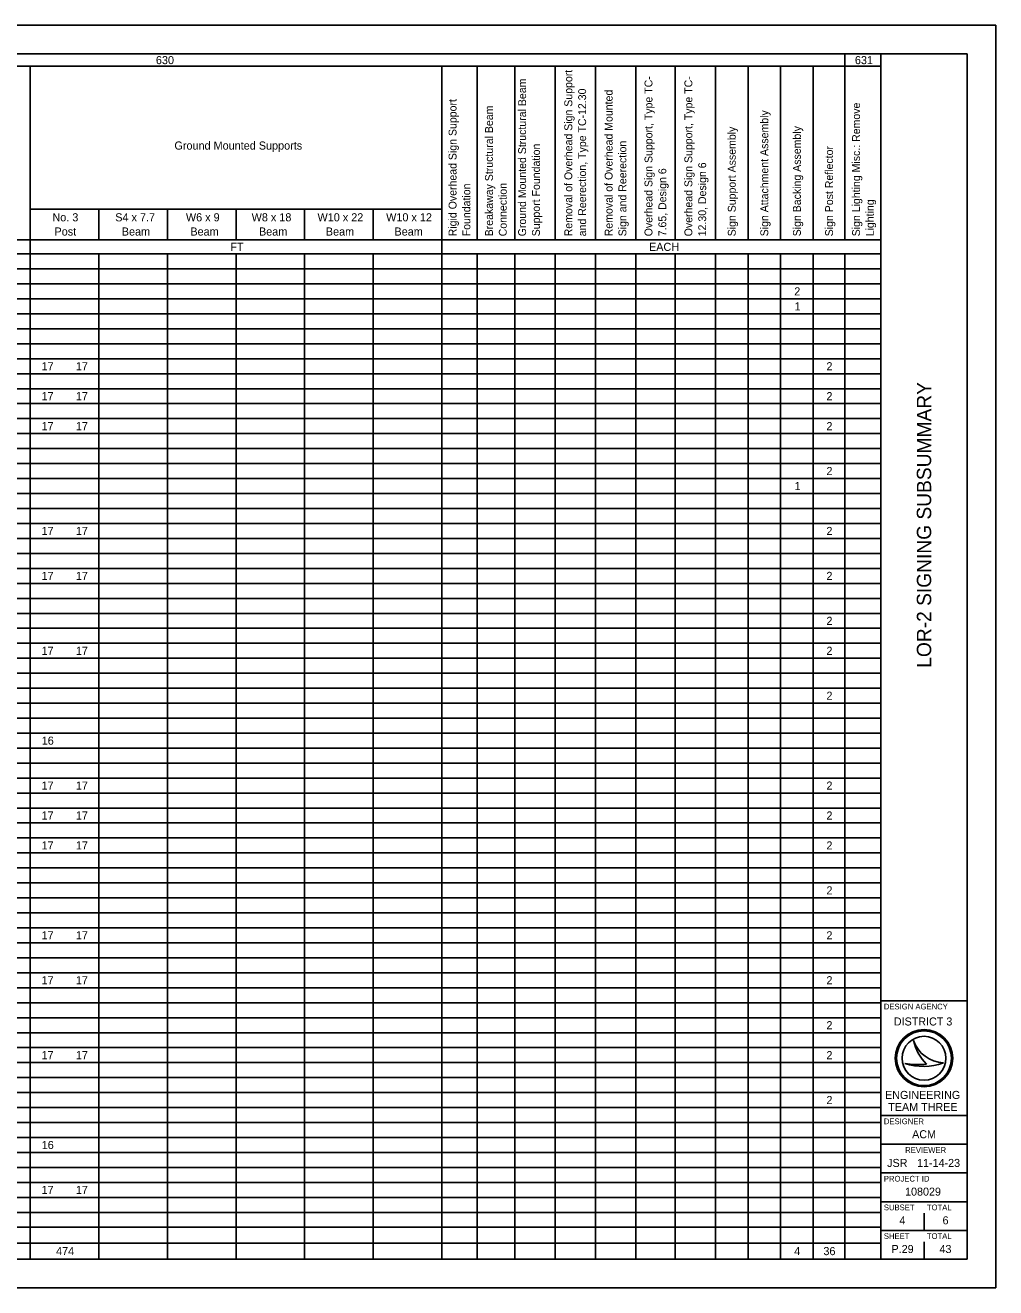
# Model space of a CAD drawing. Extents: x 0 to 34, y 0 to 22.
# Drawn here: x 17.09 to 34, y 0 to 22 of the extents above; entities that cross this region are included whole.
import ezdxf

# ---------------------------------------------------------------- set-up
doc = ezdxf.new("R2010")
doc.units = 0
for name, color, linetype in [('SH_Border', 7, 'Continuous'), ('SH_Cut_Line', 7, 'Continuous'), ('SH_Data', 7, 'Continuous'), ('SH_Text', 7, 'Continuous')]:
    doc.layers.add(name, color=color, linetype=linetype)

msp = doc.modelspace()

# ---------------------------------------------------------------- linework, layer by layer
at = {"layer": 'SH_Border'}
for p, q in [((32, 0.5), (32, 21.5)), ((32, 5), (33.5, 5)), ((32, 3), (33.5, 3)), ((32, 2.5), (33.5, 2.5)), ((32, 2), (33.5, 2)), ((32, 1.5), (33.5, 1.5)), ((32, 1), (33.5, 1))]:
    msp.add_line(p, q, dxfattribs=at)
msp.add_lwpolyline([(1.5, 21.5), (33.5, 21.5), (33.5, 0.5), (1.5, 0.5)], close=True, dxfattribs=at)
at = {"layer": 'SH_Cut_Line'}
msp.add_lwpolyline([(0, 0), (34, 0), (34, 22), (0, 22)], close=True, dxfattribs=at)
at = {"layer": 'SH_Data'}
for p, q in [((32.567, 4.31), (32.567, 4.31)), ((32.75, 4), (32.75, 4)), ((32.417, 3.91), (32.417, 3.91)), ((33.087, 3.919), (33.087, 3.919)), ((32.75, 1), (32.75, 1.3)), ((32.375, 0.675), (32.375, 0.675)), ((32.75, 0.5), (32.75, 0.8))]:
    msp.add_line(p, q, dxfattribs=at)
for radius in [0.5, 0.477, 0.477, 0.382]:
    msp.add_circle((32.75, 4), radius, dxfattribs=at)
for centre, radius, start, end in [((33.116, 4.498), 0.58, 198.9257, 198.9319), ((33.347, 4.47), 0.796, 191.6379, 191.6421), ((33.116, 4.498), 0.58, 198.9319, 267.1657), ((33.347, 4.47), 0.796, 191.6421, 226.0947), ((32.739, 4.87), 1.013, 251.4576, 290.0832), ((32.648, 5.154), 1.266, 259.4964, 259.4995), ((32.739, 4.87), 1.013, 251.4527, 251.4576), ((32.648, 5.154), 1.266, 259.4995, 276.6672)]:
    msp.add_arc(centre, radius, start, end, dxfattribs=at)
at = {"layer": 'SH_Text'}
for p, q in [((1.5, 21.5), (32, 21.5)), ((31.372, 21.5), (31.372, 18.261)), ((32, 21.5), (32, 18.015)), ((7.657, 21.285), (32, 21.285)), ((17.176, 21.285), (17.176, 18.015)), ((24.349, 21.285), (24.349, 18.015)), ((24.962, 21.285), (24.962, 18.261)), ((25.619, 21.285), (25.619, 18.261)), ((26.321, 21.285), (26.321, 18.261)), ((27.024, 21.285), (27.024, 18.261)), ((27.726, 21.285), (27.726, 18.261)), ((28.414, 21.285), (28.414, 18.261)), ((29.116, 21.285), (29.116, 18.261)), ((29.684, 21.285), (29.684, 18.261)), ((30.252, 21.285), (30.252, 18.261)), ((30.819, 21.285), (30.819, 18.261)), ((17.176, 18.798), (24.349, 18.798)), ((18.371, 18.798), (18.371, 18.261)), ((19.567, 18.798), (19.567, 18.261)), ((20.762, 18.798), (20.762, 18.261)), ((21.958, 18.798), (21.958, 18.261)), ((23.153, 18.798), (23.153, 18.261)), ((6.521, 18.261), (32, 18.261)), ((1.5, 18.015), (32, 18.015)), ((17.176, 18.015), (17.176, 0.5)), ((18.371, 18.015), (18.371, 0.5)), ((19.567, 18.015), (19.567, 0.5)), ((20.762, 18.015), (20.762, 0.5)), ((21.958, 18.015), (21.958, 0.5)), ((23.153, 18.015), (23.153, 0.5)), ((24.349, 18.015), (24.349, 0.5)), ((24.962, 18.015), (24.962, 0.5)), ((25.619, 18.015), (25.619, 0.5)), ((26.321, 18.015), (26.321, 0.5)), ((27.024, 18.015), (27.024, 0.5)), ((27.726, 18.015), (27.726, 0.5)), ((28.414, 18.015), (28.414, 0.5)), ((29.116, 18.015), (29.116, 0.5)), ((29.684, 18.015), (29.684, 0.5)), ((30.252, 18.015), (30.252, 0.5)), ((30.819, 18.015), (30.819, 0.5)), ((31.372, 18.015), (31.372, 0.5)), ((32, 18.015), (32, 0.5)), ((1.5, 17.754), (32, 17.754)), ((1.5, 17.493), (32, 17.493)), ((1.5, 17.232), (32, 17.232)), ((1.5, 16.971), (32, 16.971)), ((1.5, 16.711), (32, 16.711)), ((1.5, 16.45), (32, 16.45)), ((1.5, 16.189), (32, 16.189)), ((1.5, 15.928), (32, 15.928)), ((1.5, 15.667), (32, 15.667)), ((1.5, 15.406), (32, 15.406)), ((1.5, 15.145), (32, 15.145)), ((1.5, 14.884), (32, 14.884)), ((1.5, 14.623), (32, 14.623)), ((1.5, 14.362), (32, 14.362)), ((1.5, 14.101), (32, 14.101)), ((1.5, 13.84), (32, 13.84)), ((1.5, 13.579), (32, 13.579)), ((1.5, 13.318), (32, 13.318)), ((1.5, 13.057), (32, 13.057)), ((1.5, 12.796), (32, 12.796)), ((1.5, 12.535), (32, 12.535)), ((1.5, 12.274), (32, 12.274)), ((1.5, 12.013), (32, 12.013)), ((1.5, 11.752), (32, 11.752)), ((1.5, 11.491), (32, 11.491)), ((1.5, 11.23), (32, 11.23)), ((1.5, 10.969), (32, 10.969)), ((1.5, 10.708), (32, 10.708)), ((1.5, 10.447), (32, 10.447)), ((1.5, 10.186), (32, 10.186)), ((1.5, 9.925), (32, 9.925)), ((1.5, 9.664), (32, 9.664)), ((1.5, 9.404), (32, 9.404)), ((1.5, 9.143), (32, 9.143)), ((1.5, 8.882), (32, 8.882)), ((1.5, 8.621), (32, 8.621)), ((1.5, 8.36), (32, 8.36)), ((1.5, 8.099), (32, 8.099)), ((1.5, 7.838), (32, 7.838)), ((1.5, 7.577), (32, 7.577)), ((1.5, 7.316), (32, 7.316)), ((1.5, 7.055), (32, 7.055)), ((1.5, 6.794), (32, 6.794)), ((1.5, 6.533), (32, 6.533)), ((1.5, 6.272), (32, 6.272)), ((1.5, 6.011), (32, 6.011)), ((1.5, 5.75), (32, 5.75)), ((1.5, 5.489), (32, 5.489)), ((1.5, 5.228), (32, 5.228)), ((1.5, 4.967), (32, 4.967)), ((1.5, 4.706), (32, 4.706)), ((1.5, 4.445), (32, 4.445)), ((1.5, 4.184), (32, 4.184)), ((1.5, 3.923), (32, 3.923)), ((1.5, 3.662), (32, 3.662)), ((1.5, 3.401), (32, 3.401)), ((1.5, 3.14), (32, 3.14)), ((1.5, 2.879), (32, 2.879)), ((1.5, 2.618), (32, 2.618)), ((1.5, 2.357), (32, 2.357)), ((1.5, 2.096), (32, 2.096)), ((1.5, 1.836), (32, 1.836)), ((1.5, 1.575), (32, 1.575)), ((1.5, 1.314), (32, 1.314)), ((1.5, 1.053), (32, 1.053)), ((1.5, 0.776), (32, 0.776)), ((1.5, 0.5), (32, 0.5))]:
    msp.add_line(p, q, dxfattribs=at)

# ---------------------------------------------------------------- texts
at = {"layer": 'SH_Data'}
msp.add_text('LOR-2 SIGNING SUBSUMMARY', height=0.25, rotation=90, dxfattribs=at).set_placement((32.875, 10.804))
for s, height, p in [('DESIGN AGENCY', 0.1, (32.05, 4.85)), ('DISTRICT 3', 0.14, (32.224, 4.57)), ('ENGINEERING', 0.14, (32.071, 3.29)), ('TEAM THREE', 0.14, (32.127, 3.08)), ('DESIGNER', 0.1, (32.05, 2.85)), ('ACM', 0.14, (32.543, 2.605)), ('REVIEWER', 0.1, (32.422, 2.35)), ('JSR', 0.14, (32.108, 2.105)), ('11-14-23', 0.14, (32.629, 2.105)), ('PROJECT ID', 0.1, (32.05, 1.85)), ('SUBSET', 0.1, (32.05, 1.35)), ('TOTAL', 0.1, (32.8, 1.35)), ('4', 0.14, (32.322, 1.105)), ('6', 0.14, (33.073, 1.105)), ('SHEET', 0.1, (32.05, 0.85)), ('TOTAL', 0.1, (32.8, 0.85)), ('P.29', 0.14, (32.184, 0.605)), ('43', 0.14, (33.02, 0.605))]:
    msp.add_text(s, height=height, dxfattribs=at).set_placement(p)
at = {"layer": 'SH_Text'}
for s, height, p in [('630', 0.1412, (19.366, 21.322)), ('631', 0.1412, (31.546, 21.322)), ('Ground Mounted Supports', 0.14123, (19.689, 19.833)), ('No. 3', 0.1412, (17.563, 18.583)), ('S4 x 7.7', 0.1412, (18.658, 18.583)), ('W6 x 9', 0.1412, (19.889, 18.583)), ('W8 x 18', 0.1412, (21.034, 18.583)), ('W10 x 22 ', 0.1412, (22.182, 18.583)), ('W10 x 12 ', 0.1412, (23.378, 18.583)), ('Post', 0.1412, (17.599, 18.335)), (' Beam', 0.1412, (18.719, 18.335)), (' Beam', 0.1412, (19.914, 18.335)), (' Beam', 0.1412, (21.11, 18.335)), ('Beam', 0.1412, (22.327, 18.335)), ('Beam', 0.1412, (23.523, 18.335)), ('FT', 0.1412, (20.663, 18.068)), ('EACH', 0.1412, (27.958, 18.068)), ('2', 0.141, (30.489, 17.292)), ('1', 0.141, (30.495, 17.031)), ('17', 0.1412, (17.373, 15.987)), ('17', 0.1412, (17.971, 15.987)), ('2', 0.141, (31.05, 15.987)), ('17', 0.1412, (17.373, 15.466)), ('17', 0.1412, (17.971, 15.466)), ('2', 0.141, (31.05, 15.466)), ('17', 0.1412, (17.373, 14.944)), ('17', 0.1412, (17.971, 14.944)), ('2', 0.141, (31.05, 14.944)), ('2', 0.141, (31.05, 14.161)), ('1', 0.141, (30.495, 13.9)), ('17', 0.1412, (17.373, 13.117)), ('17', 0.1412, (17.971, 13.117)), ('2', 0.141, (31.05, 13.117)), ('17', 0.1412, (17.373, 12.334)), ('17', 0.1412, (17.971, 12.334)), ('2', 0.141, (31.05, 12.334)), ('2', 0.141, (31.05, 11.551)), ('17', 0.1412, (17.373, 11.029)), ('17', 0.1412, (17.971, 11.029)), ('2', 0.141, (31.05, 11.029)), ('2', 0.141, (31.05, 10.246)), ('16', 0.1412, (17.376, 9.463)), ('17', 0.1412, (17.373, 8.68)), ('17', 0.1412, (17.971, 8.68)), ('2', 0.141, (31.05, 8.68)), ('17', 0.1412, (17.373, 8.159)), ('17', 0.1412, (17.971, 8.159)), ('2', 0.141, (31.05, 8.159)), ('17', 0.1412, (17.373, 7.637)), ('17', 0.1412, (17.971, 7.637)), ('2', 0.141, (31.05, 7.637)), ('2', 0.141, (31.05, 6.854)), ('17', 0.1412, (17.373, 6.071)), ('17', 0.1412, (17.971, 6.071)), ('2', 0.141, (31.05, 6.071)), ('17', 0.1412, (17.373, 5.288)), ('17', 0.1412, (17.971, 5.288)), ('2', 0.141, (31.05, 5.288)), ('2', 0.141, (31.05, 4.505)), ('17', 0.1412, (17.373, 3.983)), ('17', 0.1412, (17.971, 3.983)), ('2', 0.141, (31.05, 3.983)), ('2', 0.141, (31.05, 3.2)), ('16', 0.1412, (17.376, 2.417)), ('17', 0.1412, (17.373, 1.634)), ('17', 0.1412, (17.971, 1.634)), ('108029', 0.14, (32.42, 1.605)), ('474', 0.1412, (17.627, 0.568)), ('4', 0.141, (30.488, 0.568)), ('36', 0.1412, (30.997, 0.568))]:
    msp.add_text(s, height=height, dxfattribs=at).set_placement(p)
for s, height, p in [('Removal of Overhead Sign Support ', 0.13748, (26.621, 18.322)), ('Ground Mounted Structural Beam ', 0.13748, (25.816, 18.322)), ('Overhead Sign Support, Type TC-', 0.13748, (28.018, 18.322)), ('Overhead Sign Support, Type TC-', 0.13748, (28.713, 18.322)), ('Rigid Overhead Sign Support ', 0.13748, (24.604, 18.322)), ('and Reerection, Type TC-12.30', 0.13748, (26.862, 18.322)), ('Removal of Overhead Mounted    ', 0.13748, (27.323, 18.322)), ('Breakaway Structural Beam ', 0.13748, (25.239, 18.322)), ('Sign Attachment Assembly', 0.13748, (30.036, 18.322)), ('Sign Lighting Misc.: Remove ', 0.13748, (31.635, 18.322)), ('Sign Backing Assembly', 0.13748, (30.604, 18.322)), ('Sign Support Assembly', 0.13748, (29.469, 18.322)), ('Support Foundation', 0.13748, (26.057, 18.322)), ('Sign and Reerection', 0.13748, (27.564, 18.322)), ('Sign Post Reflector', 0.13748, (31.165, 18.322)), ('12.30, Design 6', 0.13748, (28.954, 18.322)), ('7.65, Design 6', 0.13748, (28.259, 18.322)), ('Foundation', 0.1375, (24.844, 18.322)), ('Connection', 0.1375, (25.479, 18.322)), ('Lighting', 0.1375, (31.875, 18.322))]:
    msp.add_text(s, height=height, rotation=90, dxfattribs=at).set_placement(p)

doc.saveas('drawing.dxf')
